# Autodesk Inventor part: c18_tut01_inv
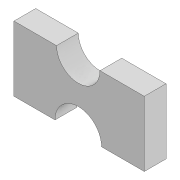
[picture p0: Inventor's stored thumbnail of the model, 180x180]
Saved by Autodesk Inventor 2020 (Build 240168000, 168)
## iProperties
Created: 2019-07
Part Number: c18_tut01_inv
Material: Generic
Document SubType Name: Modeling
Designer: LENOVO-CADCIM
Density: 1 g/cm^3
Appearance: Default
Author: LENOVO-CADCIM
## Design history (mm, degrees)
sketch "Sketch1"
  geometry: L1 (-29.598, 12.811)-(-10, 12.811); L2 (10, 12.811)-(30.402, 12.811); L3 (30.402, 12.811)-(30.402, -17.189); L4 (30.402, -17.189)-(10.723, -17.189); L5 (-10.723, -17.189)-(-29.598, -17.189); L6 (-29.598, -17.189)-(-29.598, 12.811); A1 r 10 centre (0, 12.811) between (-10, 12.811) and (10, 12.811); A2 r 10.723 centre (0, -17.189) between (10.723, -17.189) and (-10.723, -17.189); 1 further point
  constraints: 12 end point, 6 point on line, 4 point on circle, 3 perpendicular, 2 centre point, 1 horizontal
  dimensions: "d0" = 60 distance between parallel lines of L3 L6 (= LEN); "d1" = 30 distance of L5.end L1.start (= WID); "d2" = 10 radius of A1 (= RAD)
extrude "Extrusion1" new body sketch "Sketch1" distance "d3" = 10; taper "d4" = 0 deg
body "Solid1"
other parameters: "LEN" = 60 [user parameter; used in 4 equation terms], "WID" = 30 (= 0.5 x LEN) [user parameter; used in 1 equation term], "RAD" = 10 (= 0.166667 x LEN) [user parameter; used in 1 equation term]
